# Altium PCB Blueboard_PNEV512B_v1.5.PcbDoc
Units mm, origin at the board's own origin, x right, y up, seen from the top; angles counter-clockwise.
Board outline 183.2 x 34.6 mm, 2 copper layers (Top Layer, Bottom Layer), stack 1.62 mm thick; 130 components, 72 nets, 392 pads, 149 vias.
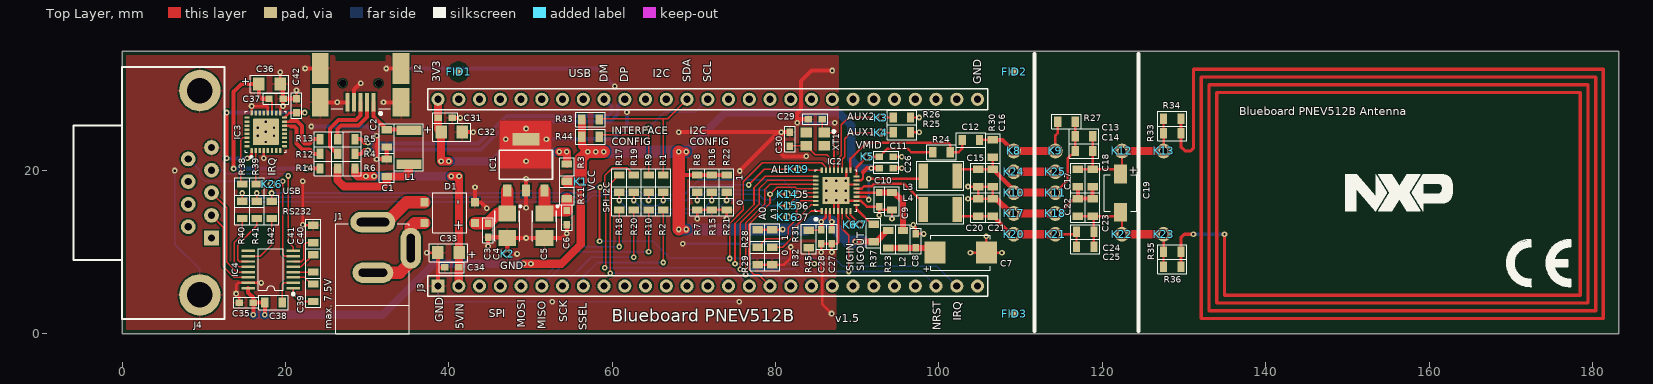
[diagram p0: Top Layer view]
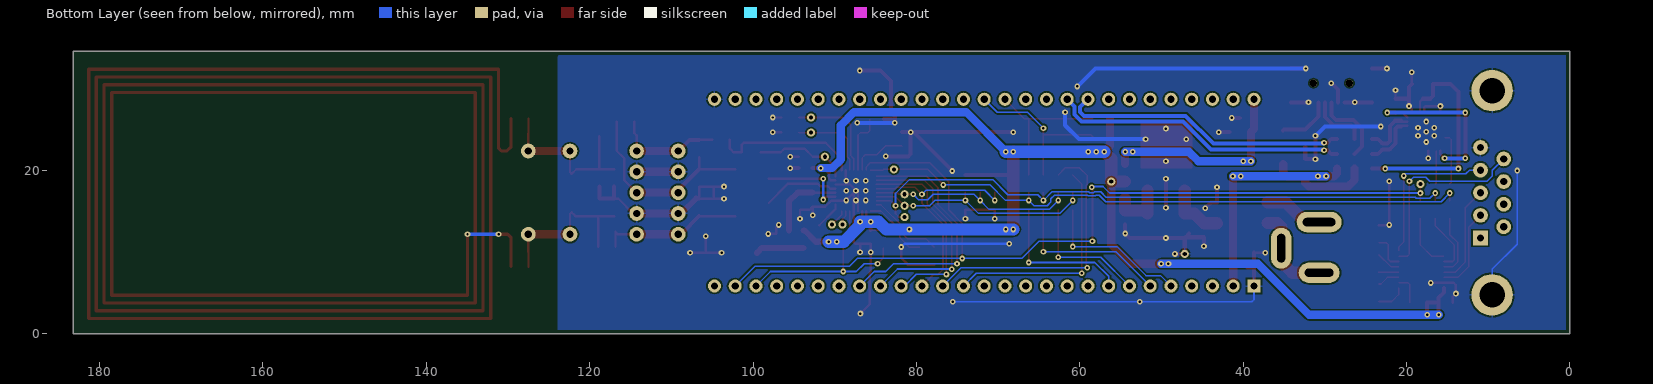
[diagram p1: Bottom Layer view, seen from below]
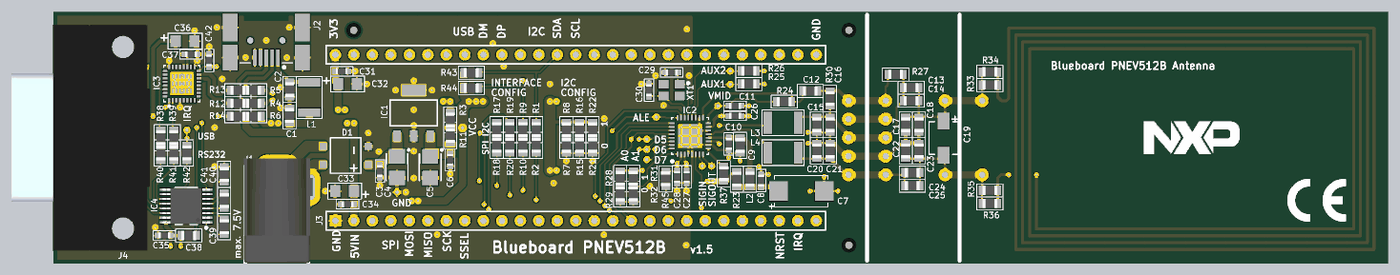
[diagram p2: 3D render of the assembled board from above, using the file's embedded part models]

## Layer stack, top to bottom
Top Layer: signal copper 0.035
Dielectric: core 1.55, FR-4, Dk 4.3
Bottom Layer: signal copper 0.035

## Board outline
0,0 183.2,0 183.2,34.6 0,34.6

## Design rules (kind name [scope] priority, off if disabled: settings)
Clearance [All] p1: gap=0.2
ComponentClearance [All] p1: gap=0 collisioncheckmode=3 verticalgap=0 showdistances=FALSE
DiffPairsRouting [(InDifferentialPairClass('All Differential Pairs'))] p1: maxlimit=0.2 minlimit=0.2 mostfreqgap=0.2 maxuncoupledlength=12.7
FabricationTestPointUsage TestPointUsage [All] p1: valid=0 allowmultiple=FALSE
FabricationTestpoint Testpoint [All] p1: side=3 testpointundercomponent=TRUE minsize=1.016 maxsize=2.54 preferedsize=1.524 minholesize=0 maxholesize=1.016 preferedholesize=0.813 testpointgrid=0.025 allowsidetop=TRUE allowsidebottom=TRUE usegrid=TRUE gridtolerance=0
HoleSize [All] p1: absolutevalues=TRUE maxlimit=6.3 minlimit=0.1 maxpercent=80.000 minpercent=20.000
PlaneClearance [All] p1: clearance=0.5
PlaneConnect [All] p1: planeconnectstyle=Relief reliefexpansion=0.2 reliefentries=4 reliefconductorwidth=0.2 reliefairgap=0.2
PolygonConnect PolygonConnect_Via [IsVia] p1: connectstyle=Direct reliefconductorwidth=0.254 reliefentries=4 polygonreliefangle="90 Angle"
PolygonConnect [All] p2: connectstyle=Relief reliefconductorwidth=0.25 reliefentries=4 polygonreliefangle="90 Angle"
RoutingVias [All] p1: holewidth=0.3 width=0.7 viastyle="Through Hole" minholewidth=0.3 minwidth=0.7 maxholewidth=0.6 maxwidth=1
SilkscreenOverComponentPads [All] p1: minsilkscreentomaskgap=0.254
SolderMaskExpansion SolderMaskExpansion_Via [IsVia] p1: expansion=-0.1
SolderMaskExpansion [All] p2: expansion=0.1
Width Width_DiffPair [(InDifferentialPairClass('All Differential Pairs'))] p1: maxlimit=0.5 minlimit=0.3 preferedwidth=0.5
Width [All] p2: maxlimit=3 minlimit=0.2 preferedwidth=0.2
20 further rules are at their usual default settings.

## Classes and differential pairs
differential pair USB: +USB_P -USB_N
differential pair LPC_USB: +LPC_USB_P -LPC_USB_N

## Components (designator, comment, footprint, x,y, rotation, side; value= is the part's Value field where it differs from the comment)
C1 "1uF" Y0805 32.4,20.35 r270 top
C2 "1uF" Y0805 32.4,23.95 r90 top
C3 "100nF" Y0603 44.8,12.7 r270 top
C4 "33uF/16V" C_TANTAL_B 47.15,13.25 r270 top
C5 "33uF/16V" C_TANTAL_B 51.7,13.25 r270 top
C6 "100nF" Y0603 54.45,14.25 r270 top
C7 "100uF" C_TANTAL_D 102.65,9.95 r0 top
C8 "100nF" Y0603 97.15,11.4 r270 top
C9 "1uF" Y0805 94.25,16.25 r90 top
C10 "100nF" Y0603 92.7,16.45 r90 top
C11 "100nF" Y0603 93.55,21.7 r0 top
C12 "1nF" Y0805 103.9,23.75 r0 top
C13 "12pF" Y0805 117.75,24.2 r0 top
C14 "33pF" Y0805 117.75,22.4 r0 top
C15 "100pF" Y0805 104.8,19.1 r90 top
C16 "56pF" Y0805 106.6,19.1 r90 top
C17 "100pF" Y0805 117,19.1 r90 top
C18 "39pF" Y0805 118.8,19.1 r90 top
C19 "TZB4A 25pF" C_TZB4_A 122.2,17.25 r270 top
C20 "100pF" Y0805 104.8,15.5 r90 top
C21 "56pF" Y0805 106.6,15.5 r90 top
C22 "100pF" Y0805 117,15.5 r90 top
C23 "39pF" Y0805 118.8,15.5 r90 top
C24 "33pF" Y0805 117.9,12.5 r0 top
C25 "12pF" Y0805 117.9,10.7 r0 top
C26 "100nF" Y0603 93.55,20.3 r180 top
C27 "100nF" Y0603 86.9,11.9 r90 top
C28 "100nF" Y0603 85.6,11.9 r90 top
C29 "15pF" Y0603 84.85,26.3 r0 top
C30 "15pF" Y0603 81.75,23.85 r270 top
C31 "100nF" Y0603 39.55,26.45 r180 top
C32 "10uF/10V" CAP_TANT_1206_CASE-A 40.35,24.7 r0 top
C33 "10uF/10V" CAP_TANT_1206_CASE-A 39.95,9.95 r180 top
C34 "100nF" Y0603 40.35,8.15 r0 top
C35 "100nF" Y0603 15.2,3.85 r180 top
C36 "10uF/10V" CAP_TANT_1206_CASE-A 18.05,30.6 r0 top
C37 "100nF" Y0603 18.85,28.8 r180 top
C38 "1uF" Y0805 18.55,3.85 r0 top
C39 "1uF" Y0805 23.4,5.05 r90 top
C40 "1uF" Y0805 23.4,12.25 r90 top
C41 "1uF" Y0805 23.4,8.65 r90 top
C42 "100nF" Y0603 21.35,27.95 r270 top
D1 "CDBHM240L" GRETZ_MBS2 40.1,14.85 r270 top
FID1 "{Value}" FIDUCIAL_40 41.2,32.1 r0 top
FID2 "{Value}" FIDUCIAL_40 109.2,32.1 r0 top
FID3 "{Value}" FIDUCIAL_40 109.2,2.5 r0 top
IC1 "LM3940IMP-3.3" SOT-223-3 47.15,17.55 r0 top
IC2 "PN512" QFN50P500X500X100-32N 87.4,17.55 r90 top
IC3 "FT232RQ" QFN-32_FTDI 17.6,24.75 r90 top
IC4 "SP3232" TSSOP-PW_16_065 18.2,7.9 r180 top
J1 "PWR_DC_PJ-202B" CON_JCK_2.5mm 30.7,7.5 r90 top locked
J2 "USB_Mini_B" CON_USB-B-MINI_SD-67503-010 29.2,28.35 r270 top locked
J3 "LPCXpresso" "CON_LPCXpresso 2X27" 71.7,17.3 r0 top locked
J4 "DSUB 9F" CON_DB9_F 10.95,11.75 r90 top locked
K1 "TP1" TESTP_ROUND_1.0mm#1 56.15,18.65 r90 top
K2 "TP1" TESTP_ROUND_1.0mm#1 47.15,9.8 r180 top
K3 "TP1" TESTP_ROUND_1.0mm#1 92.9,26.5 r270 top
K4 "TP1" TESTP_ROUND_1.0mm#2 92.95,26.65 r0 top
K5 "TP1" TESTP_ROUND_1.0mm#1 91.2,21.7 r90 top
K6 "TP1" TESTP_ROUND_1.0mm#1 89.05,13.4 r0 top
K7 "TP1" TESTP_ROUND_1.0mm#1 90.35,13.4 r0 top
K8 "TP_0.9mm" TP_0.9mm 109.15,22.4 r0 top
K9 "TP_0.9mm" TP_0.9mm 114.25,22.4 r0 top
K10 "TP_0.9mm" TP_0.9mm 109.149,17.302 r0 top
K11 "TP_0.9mm" TP_0.9mm 114.249,17.302 r0 top
K12 "TP_0.9mm" TP_0.9mm 122.4,22.4 r90 top
K13 "TP_0.9mm" TP_0.9mm 127.5,22.4 r0 top
K14 "TP1" TESTP_ROUND_1.0mm#1 81.45,17.1 r90 top
K15 "TP1" TESTP_ROUND_1.0mm#1 81.45,15.7 r90 top
K16 "TP1" TESTP_ROUND_1.0mm#1 81.45,14.3 r90 top
K17 "TP_0.9mm" TP_0.9mm 109.149,14.752 r0 top
K18 "TP_0.9mm" TP_0.9mm 114.249,14.752 r0 top
K19 "TP1" TESTP_ROUND_1.0mm#1 82.75,20.15 r90 top
K20 "TP_0.9mm" TP_0.9mm 109.149,12.202 r0 top
K21 "TP_0.9mm" TP_0.9mm 114.249,12.202 r0 top
K22 "TP_0.9mm" TP_0.9mm 122.4,12.2 r0 top
K23 "TP_0.9mm" TP_0.9mm 127.5,12.2 r0 top
K24 "TP_0.9mm" TP_0.9mm 109.149,19.863 r0 top
K25 "TP_0.9mm" TP_0.9mm 114.249,19.863 r0 top
K26 "TP1" TESTP_ROUND_1.0mm#1 18.3,18.35 r0 top
L1 "100nH" INDCC_1812 35.1,22.85 r270 top
L2 "22nH" Y0805 95.6,11.6 r270 top
L3 "470nH / shielded (1210)" INDCC_1812 100.15,19.35 r0 top
L4 "470nH / shielded (1210)" INDCC_1812 100.15,15.25 r0 top
R1 "0R DNP" Y0805 66.25,18.4 r270 top
R2 "0R" Y0805 66.25,16.25 r270 top
R3 "0R" Y0805 54.45,19.75 r90 top
R4 "0R" Y0805 27.45,22.05 r0 top
R5 "0R" Y0805 27.45,23.85 r0 top
R6 "0R" Y0805 27.45,20.25 r0 top
R7 "1k DNP" Y0805 70.4,16.25 r90 top
R8 "1k DNP" Y0805 70.4,18.4 r90 top
R9 "0R DNP" Y0805 64.45,18.4 r270 top
R10 "0R" Y0805 64.45,16.25 r270 top
R11 "0R DNP" Y0805 54.45,17.6 r90 top
R12 "0R DNP" Y0805 25.3,22.05 r0 top
R13 "0R DNP" Y0805 25.3,23.85 r0 top
R14 "0R DNP" Y0805 25.3,20.25 r0 top
R15 "1k DNP" Y0805 72.2,16.25 r90 top
R16 "1k DNP" Y0805 72.2,18.4 r90 top
R17 "0R DNP" Y0805 60.85,18.4 r270 top
R18 "0R" Y0805 60.85,16.25 r270 top
R19 "0R DNP" Y0805 62.65,18.4 r270 top
R20 "0R" Y0805 62.65,16.25 r270 top
R21 "1k DNP" Y0805 74,16.25 r90 top
R22 "1k DNP" Y0805 74,18.4 r90 top
R23 "0R" Y0805 93.8,11.6 r90 top
R24 "1k" Y0805 100.3,22.25 r180 top
R25 "DNP" Y0805 95.45,24.7 r180 top
R26 "DNP" Y0805 95.45,26.5 r180 top
R27 "2k7" Y0805 115.6,26 r180 top
R28 "0R" Y0805 77.8,11.7 r270 top
R29 "0R DNP" Y0805 77.8,9.55 r270 top
R30 "DNP" Y0805 106.6,22.7 r270 top
R31 "0R DNP" Y0805 79.6,11.7 r270 top
R32 "0R" Y0805 79.6,9.55 r270 top
R33 "4R42" Y0805 128.55,24.55 r180 top
R34 "4R42" Y0805 128.55,26.35 r180 top
R35 "4R42" Y0805 128.55,10.05 r180 top
R36 "4R42" Y0805 128.55,8.25 r180 top
R37 "0R DNP" Y0805 92,12.35 r90 top
R38 "0R DNP" Y0805 14.7,17.3 r90 top
R39 "0R DNP" Y0805 16.5,17.3 r90 top
R40 "0R DNP" Y0805 14.7,15.2 r90 top
R41 "0R DNP" Y0805 16.5,15.2 r90 top
R42 "0R DNP" Y0805 18.3,15.2 r270 top
R43 "10k" Y0805 57.35,26.25 r0 top
R44 "10k" Y0805 57.35,24.15 r0 top
R45 "10k" Y0805 84.049,11.633 r270 top
XT1 "27.12MHz" QUARTZ_32SMX 84.85,23.85 r180 top

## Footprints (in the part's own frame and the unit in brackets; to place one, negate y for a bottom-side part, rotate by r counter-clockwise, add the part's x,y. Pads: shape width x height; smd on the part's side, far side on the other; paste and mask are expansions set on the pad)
C_TANTAL_B [mm] "Capacitor, SM Tantalum; Body 3.5 x 2.8 mm, Size B"
  rect 2x2.2 smd: 1(-1.5,0) 2(1.5,0)
  silkscreen extent -2.5,-1.5 1.85,1.73, body extent -1.85,-1.5 1.85,1.5, height 2.11
C_TANTAL_D [mm]
  rect 2.55x2.7 smd: 1(-3.15,0) 2(3.15,0)
  silkscreen extent -3.65,-2.15 3.65,2.15, body extent -3.8,-2.25 3.8,2.25, height 3.11
C_TZB4_A [mm] "Murata Ceramic Trimmer Capacitors TZB4 Series, Type A"
  rect 2.3x1.6 smd: 1(-2.35,0) 2(2.35,0)
  silkscreen extent -2.25,-2 2.25,2, body extent -2.25,-2 2.25,2, height 3
CAP_TANT_1206_CASE-A [mm] "AVX"
  rect 1.4x1.6 smd: 1(-1.3,0) 2(1.3,0)
  silkscreen extent -2.34,-1.1 2.34,1.1
CON_DB9_F [mm]
  rect 1.8x1.8 hole 0.9: 1(0,0)
  round 1.8 hole 0.9: 2(2.769,0) 3(5.537,0) 4(8.306,0) 5(11.074,0) 6(1.372,2.845) 7(4.14,2.845) 8(6.909,2.845) 9(9.677,2.845)
  round 5.08 hole 3.1: 10(-6.96,1.422) 11(18.034,1.422)
  silkscreen extent -9.9,-1.59 20.95,16.92, body extent -10,-2.25 21.1,16.74, height 12.42
CON_JCK_2.5mm [mm]
  oval 2.5x5.5 hole 1 slot 4 at 90 deg: 1(6.2,0)
  oval 2.5x5 hole 1 slot 3.5 at 90 deg: 2(0,0)
  oval 5x2.5 hole 1 slot 3.5 at 0 deg: 3(3,-4.65)
  silkscreen extent -7.5,-4.45 6,4.55, body extent -7.5,-4.86 6.98,4.61, height 11.18
"CON_LPCXpresso 2X27" [mm]
  rect 1.6x1.6 hole 0.9: 1(-33.02,-11.43)
  round 1.6 hole 0.9: 2(-30.48,-11.43) 3(-27.94,-11.43) 4(-25.4,-11.43) 5(-22.86,-11.43) 6(-20.32,-11.43) 7(-17.78,-11.43) 8(-15.24,-11.43) 9(-12.7,-11.43) 10(-10.16,-11.43) 11(-7.62,-11.43) 12(-5.08,-11.43) 13(-2.54,-11.43) 14(0,-11.43) 15(2.54,-11.43) 16(5.08,-11.43) 17(7.62,-11.43) 18(10.16,-11.43) 19(12.7,-11.43) 20(15.24,-11.43) 21(17.78,-11.43) 22(20.32,-11.43) 23(22.86,-11.43) 24(25.4,-11.43) 25(27.94,-11.43) 26(30.48,-11.43) 27(33.02,-11.43) 28(-33.02,11.43) 29(-30.48,11.43) 30(-27.94,11.43) 31(-25.4,11.43) 32(-22.86,11.43) 33(-20.32,11.43) 34(-17.78,11.43) 35(-15.24,11.43) 36(-12.7,11.43) 37(-10.16,11.43) 38(-7.62,11.43) 39(-5.08,11.43) 40(-2.54,11.43) 41(0,11.43) 42(2.54,11.43) 43(5.08,11.43) 44(7.62,11.43) 45(10.16,11.43) 46(12.7,11.43) 47(15.24,11.43) 48(17.78,11.43) 49(20.32,11.43) 50(22.86,11.43) 51(25.4,11.43) 52(27.94,11.43) 53(30.48,11.43) 54(33.02,11.43)
  silkscreen extent -34.29,-12.7 34.29,12.7
CON_USB-B-MINI_SD-67503-010 [mm] "Molex"
  rect 2.25x0.5 smd: 1(0,1.6) 2(0,0.8) 3(0,0) 4(0,-0.8) 5(0,-1.6)
  rect 3.8x2.05 smd: 6(-4.15,4.95) 9(-4.15,-4.95)
  rect 3.5x2.05 smd: 7(0,4.95) 8(0,-4.95)
  round 0.9 hole 0.9 unplated: 10(-2.35,2.2) 11(-2.35,-2.2)
  Top Layer pour cut-out: -6.25,3.1 -5.05,3.1 -5.05,-3.1 -6.25,-3.1
  silkscreen extent 0.75,-3.6 1.5,3.6
FIDUCIAL_40 [mm]
  round 1 smd: 1(0,0)
  Top Layer pour cut-out: 0,1.27 -0.153,1.261 -0.304,1.233 -0.45,1.187 -0.59,1.125 -0.721,1.045 -0.842,0.951 -0.951,0.842 -1.045,0.721 -1.125,0.59 -1.187,0.45 -1.233,0.304 -1.261,0.153 -1.27,0 -1.261,-0.153 -1.233,-0.304 -1.187,-0.45 -1.125,-0.59 -1.045,-0.721 -0.951,-0.842 -0.842,-0.951 -0.721,-1.045 -0.59,-1.125 -0.45,-1.187 -0.304,-1.233 -0.153,-1.261 0,-1.27 0.153,-1.261 0.304,-1.233 0.45,-1.187 0.59,-1.125 0.721,-1.045 0.842,-0.951 0.951,-0.842 1.045,-0.721 1.125,-0.59 1.187,-0.45 1.233,-0.304 1.261,-0.153 1.27,0 1.261,0.153 1.233,0.304 1.187,0.45 1.125,0.59 1.045,0.721 0.951,0.842 0.842,0.951 0.721,1.045 0.59,1.125 0.45,1.187 0.304,1.233 0.153,1.261
GRETZ_MBS2 [mm]
  rect 1x1 smd: 1(-1.27,-3.099) 2(1.27,-3.099) 3(1.27,3.099) 4(-1.27,3.099)
  silkscreen extent -2.45,-2.1 2.45,2.1
INDCC_1812 [mil]
  rect 45x120 smd: 1(-82,0) 2(82,0)
  silkscreen extent -114,-70 114,70
QFN50P500X500X100-32N [mm] "QFN, 32-Leads, Body 5.1x5.1mm (max), Pitch 0.50mm, IPC Medium Density"
  rect 0.7x0.25 smd: 1(-2.5,1.75) 2(-2.5,1.25) 3(-2.5,0.75) 4(-2.5,0.25) 5(-2.5,-0.25) 6(-2.5,-0.75) 7(-2.5,-1.25) 8(-2.5,-1.75) 17(2.5,-1.75) 18(2.5,-1.25) 19(2.5,-0.75) 20(2.5,-0.25) 21(2.5,0.25) 22(2.5,0.75) 23(2.5,1.25) 24(2.5,1.75)
  rect 0.25x0.7 smd: 9(-1.75,-2.5) 10(-1.25,-2.5) 11(-0.75,-2.5) 12(-0.25,-2.5) 13(0.25,-2.5) 14(0.75,-2.5) 15(1.25,-2.5) 16(1.75,-2.5) 25(1.75,2.5) 26(1.25,2.5) 27(0.75,2.5) 28(0.25,2.5) 29(-0.25,2.5) 30(-0.75,2.5) 31(-1.25,2.5) 32(-1.75,2.5)
  rect 3.3x3.3 smd paste-5 mask+0.102: 33(0,0)
  silkscreen extent -3.65,-2.55 2.55,2.6, body extent -2.55,-2.55 2.55,2.55, height 1
QFN-32_FTDI [mm]
  rect 0.3x0.3 smd: 1(-2.45,1.75) 8(-2.45,-1.75) 9(-1.75,-2.45) 16(1.75,-2.45) 17(2.45,-1.75) 24(2.45,1.75) 25(1.75,2.45) 32(-1.75,2.45)
  rrect50% 0.6x0.3 smd: 1(-2.3,1.75) 8(-2.3,-1.75) 17(2.3,-1.75) 24(2.3,1.75)
  rect 0.6x0.3 smd: 2(-2.3,1.25) 3(-2.3,0.75) 4(-2.3,0.25) 5(-2.3,-0.25) 6(-2.3,-0.75) 7(-2.3,-1.25) 18(2.3,-1.25) 19(2.3,-0.75) 20(2.3,-0.25) 21(2.3,0.25) 22(2.3,0.75) 23(2.3,1.25)
  rrect50% 0.3x0.6 smd: 9(-1.75,-2.3) 16(1.75,-2.3) 25(1.75,2.3) 32(-1.75,2.3)
  rect 0.3x0.6 smd: 10(-1.25,-2.3) 11(-0.75,-2.3) 12(-0.25,-2.3) 13(0.25,-2.3) 14(0.75,-2.3) 15(1.25,-2.3) 26(1.25,2.3) 27(0.75,2.3) 28(0.25,2.3) 29(-0.25,2.3) 30(-0.75,2.3) 31(-1.25,2.3)
  rrect6% 3.2x3.2 smd paste-5: 33(0,0)
  silkscreen extent -3.2,-2.5 2.5,2.5, body extent -2.5,-2.5 2.5,2.5, height 0.9
QUARTZ_32SMX [mm]
  rect 1.4x1.2 smd: 1(-1.1,-0.8) 2(1.1,-0.8) 3(1.1,0.8) 4(-1.1,0.8)
  silkscreen extent -2.42,-1.1 -2.13,-0.8, body extent -1.6,-1.2 1.6,1.2, height 0.6
SOT-223-3 [mm]
  rect 1x1.5 smd: 1(0,0) 2(2.286,0) 3(4.572,0)
  rect 3.3x1.5 smd: 4(2.286,6.299)
  silkscreen extent -0.97,1.37 5.54,4.93
TESTP_ROUND_1.0mm#1 [mm]
  round 1 hole 0.5 paste-2: 1(0,0)
TESTP_ROUND_1.0mm#2 [mm]
  round 1 hole 0.5 paste-2: 1(-0.05,-2)
TP_0.9mm [mm]
  round 1.8 hole 0.9: 1(0,0)
TSSOP-PW_16_065 [mm]
  rect 1.65x0.3 smd: 1(-2.775,2.275) 2(-2.775,1.625) 3(-2.775,0.975) 4(-2.775,0.325) 5(-2.775,-0.325) 6(-2.775,-0.975) 7(-2.775,-1.625) 8(-2.775,-2.275) 9(2.775,-2.275) 10(2.775,-1.625) 11(2.775,-0.975) 12(2.775,-0.325) 13(2.775,0.325) 14(2.775,0.975) 15(2.775,1.625) 16(2.775,2.275)
  silkscreen extent -2.9,-2.55 1.55,3.15, body extent -3.23,-2.5 3.23,2.5, height 1.2
Y0603 [mm]
  rect 0.9x0.8 smd: 1(-0.864,0) 2(0.864,0)
  silkscreen extent -1.55,-0.65 1.55,0.65, body extent -0.81,-0.42 0.81,0.4, height 0.46
Y0805 [mm]
  rect 0.9x1.27 smd: 1(-1.067,0) 2(1.067,0)
  silkscreen extent -1.8,-0.9 1.8,0.9, body extent -1.02,-0.65 1,0.62, height 0.61

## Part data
C1 C2 C9 C12 C13 C14 C15 C16 C17 C18 C20 C21 C22 C23 C24 C25 C38 C39 C40 C41: library part CAPC0805, "CAPC0805"
C3 C6 C8 C10 C11 C26 C27 C28 C29 C30 C31 C34 C35 C37 C42: library part CAPC0603, "CAPC0603"
C4 C5: library part C_TANTAL_B, "C_TANTAL_B"
C7: library part C_TANTAL_D, "C_TANTAL_D"
C19: library part C_TRIMM, "C_TRIMM"
C32 C33 C36: library part C_TANTAL_1206, "C_TANTAL_1206"
D1: library part GRETZ_MBS2, "GRETZ_MBS2_Schottky"
FID1 FID2 FID3: library part FIDUCIAL, "FIDUCAL"
IC1: library part LM3940-3.3, "LM3940-3.3"
IC3: library part FT232R, "FT232R"
J1: library part CON_JCK_2.5mm, "PWR_JACK_2.5mm x 5.5mm"
J2: library part CON_USB_B_RA, "CON_USB_B_RA"
J3: library part CON_LPCXpresso, "CON_LPCXpresso 2X27"
J4: library part CON_DB9_F, "DB9_FEMALE"
L1 L3 L4: library part INDC1812, "INDC1812"
L2: library part INDC0805, "INDC0805"
R1 R2 R3 R4 R5 R6 R7 R8 R9 R10 R11 R12 R13 R14 R15 R16 R17 R18 R19 R20 R21 R22 R23 R24 R25 R26 R27 R28 R29 R30 R31 R32 R33 R34 R35 R36 R37 R38 R39 R40 R41 R42 R43 R44 R45: library part RESC0805, "RESC0805"
XT1: library part QUARTZ_32SMX, "QUARTZ_32SMX"

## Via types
v1: diameter 0.7, hole 0.3, Top Layer to Bottom Layer, 140 vias
v2: diameter 0.7, hole 0.3, Top Layer to Bottom Layer, tented top, 9 vias

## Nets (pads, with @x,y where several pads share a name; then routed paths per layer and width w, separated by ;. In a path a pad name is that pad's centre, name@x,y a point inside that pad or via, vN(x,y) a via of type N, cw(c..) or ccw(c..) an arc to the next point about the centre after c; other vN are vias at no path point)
+3.3VLPC: C31.2 C32.1 J3.28 R3.2 | length 27
  Top Layer w1: J3.28 38.68,26.456 C31.2 38.686,25.064 C32.1 v1(39.05,21.15) v1(40,21.15) ; v1(53.5,22.3) v1(54.45,22.3) R3.2
  Bottom Layer w1: v1(39.05,21.15) v1(40,21.15) 45.5,21.15 46.65,22.3 v1(53.5,22.3) v1(54.45,22.3)
+5VLPC: C33.1 C34.2 J3.2 R6.2 | length 28.9
  Top Layer w1: R6.2 28.517,19.633 28.85,19.3 v1(29.85,19.3) v1(30.85,19.3) ; v1(40.3,19.3) v1(41.25,19.3) C33.1 41.25,8.186 C34.2 41.214,5.876 J3.2
  Bottom Layer w1: v1(29.85,19.3) v1(30.85,19.3) v1(40.3,19.3) v1(41.25,19.3)
ALE: IC2.24 K19.1 R1.2 R2.1 R38.1 R40.2 | length 76.4
  Top Layer w0.2: R40.2 v1(14.7,17.25) ; v1(66.25,16.35) R2.1 R1.2 ; v1(76.7,18.25) 78.6,20.15 K19.1 84,20.15 84.1,20.05 IC2.24
  Bottom Layer w0.2: v1(14.7,17.25) 15.75,16.2 56.816,16.2 57.616,17 58.02,17 58.112,16.908 58.982,16.908 59.074,17 63.1,17 63.55,16.55 63.55,16.15 64,15.7 65.6,15.7 v1(66.25,16.35) 69.1,16.35 71,18.25 v1(76.7,18.25)
D5: IC2.29 K14.1 R15.2 R16.1 R19.2 R20.1 | length 26
  Top Layer w0.2: v1(62.65,16.35) R20.1 R19.2 ; v1(72.2,16.35) R15.2 ; v1(80.4,17.1) K14.1 82.15,17.1 82.35,17.3 IC2.29
  Bottom Layer w0.2: v1(62.65,16.35) 63.75,15.25 71.1,15.25 v1(72.2,16.35) 72.95,17.1 77.95,17.1 78.6,16.45 79.75,16.45 v1(80.4,17.1)
D6: IC2.30 K15.1 R17.2 R18.1 R21.2 R22.1 | length 28
  Top Layer w0.2: v1(60.85,16.35) R18.1 R17.2 ; v1(74,16.35) R21.2 ; v1(80.4,15.7) K15.1 82.55,16.8 IC2.30
  Bottom Layer w0.2: v1(60.85,16.35) 62.4,14.8 72.45,14.8 v1(74,16.35) 77.75,16.35 78.4,15.7 v1(80.4,15.7)
D7: IC2.31 K16.1 R9.2 R10.1 R39.1 R41.2 | length 77.3
  Top Layer w0.2: R39.1 R41.2 v1(16.5,17.25) ; v1(64.45,16.35) R10.1 R9.2 ; K16.1 82.1,14.3 82.55,14.75 v1(82.55,15.7) 83.15,16.3 IC2.31
  Bottom Layer w0.2: v1(16.5,17.25) 17.15,16.6 18.8,16.6 18.95,16.75 56.8,16.75 57.45,17.4 58.186,17.4 58.278,17.308 58.816,17.308 58.908,17.4 63.4,17.4 v1(64.45,16.35) 65.15,17.05 68.8,17.05 70.65,18.9 80.85,18.9 82.55,17.2 v1(82.55,15.7)
GND: C1.1 C2.1 C3.2 C4.2 C5.2 C6.2 C7.2 C8.1 C9.1 C10.1 C11.2 C15.1 C16.1 C17.1 C18.1 C20.2 C21.2 C22.2 C23.2 C26.1 C27.1 C28.1 C29.1 C30.1 C31.1 C32.2 C33.2 C34.1 C35.2 C36.2 C37.1 C40.2 C42.1 D1.4 IC1.2 IC1.4 IC2.4 IC2.5 IC2.10 IC2.14 IC2.18 IC2.33 IC3.4 IC3.17 IC3.20 IC3.24 IC3.33 IC4.15 J2.4 J2.5 J2.6 J2.7 J2.8 J2.9 J3.1 J3.54 J4.5 J4.10 J4.11 K2.1 K17.1 K18.1 K24.1 K25.1 R7.1 R15.1 R21.1 R25.1 R26.1 R29.2 R32.2 | length 332.9
  Top Layer w0.3: C35.2 14.336,4.564 v1(13.95,4.95) 13.95,6 14.225,6.275 IC4.15 17.025,6.275 v1(17.05,6.25) ; IC3.24@15.85,27.05 15.85,27.2 v1(15.85,27.9) 17.7,27.9 17.85,27.75 IC3.20 ; v1(17.35,21.5) IC3.4 ; IC3.17@19.35,27.05 19.35,27.2 19.35,27.55 v1(19.7,27.9) v1@19.714,27.914 ; C36.2 v1(19.35,32.05) ; C42.1 v1(21.35,29.85) ; v1(22.1,18.7) v1(22.1,13.35) 22.133,13.317 C40.2 ; v1(37.3,9.95) C33.2 ; v1(70.4,14.1) R7.1 R15.1 R21.1 v1(74,14.1) ; R29.2 R32.2 81.033,8.483 81.85,9.3 v1(81.85,10.65) ; v1(86.85,2.5) 85.7,3.65 85.7,7.55 85.6,7.65 v1(85.6,10) C28.1 C27.1 ; v1(86.9,10) C27.1 ; IC2.4 87.15,17.3 v2(87.4,17.55) ; IC2.18 88.65,18.8 v2(88.6,18.75) IC2.33@88.15,18.3 ; IC2.14 IC2.33@88.15,18.3 ; v1(92.7,14.55) C10.1 ; v1(94.25,14.1) C9.1 93.103,15.183 C10.1 ; C11.2 v1(95.45,21.7) ; R25.1 v1(97.6,24.7) ; R26.1 v1(97.6,26.5) ; v1(96.85,13.35) 97.15,13.05 C8.1 98.136,12.264 v1(98.15,12.25) ; v1(103.55,16.55) 103.567,16.567 C20.2 ; v1(103.55,18.05) 103.567,18.033 C15.1 ; v1(103.85,9.95) C7.2 ; v1(105.8,11.95) C7.2 ; v1(107.7,9.95) C7.2 ; K18.1 114.676,14.752 116.49,16.567 C22.2 ; C27.1 87.486,11.036 87.65,11.2 IC2.5 IC2.33@87.65,17.3 ; v2(87.4,17.55) IC2.33@88.15,18.3 ; v2(87.4,17.55) IC2.33@87.65,17.3 ; IC2.33@87.65,17.3 v2(88.6,16.35) 88.65,16.3 IC2.10 90.45,16.3 91.164,15.586 C10.1 ; C20.2 C15.1 ; C20.2 C21.2 C16.1 C15.1
  Top Layer w0.5: C36.2 19.714,30.236 C37.1 ; v1@19.714,27.914 C37.1 ; C42.1 21.336,28.8 C37.1 ; v1(22.4,32.5) J2.9 ; J2.8 v1(26.35,28.35) J2.5 ; J2.4 28.4,29.9 v1(29.2,30.7) ; v1(31.15,24.25) v1(31.15,21.4) 31.167,21.417 C1.1 C2.1 ; v1(32,28.35) J2.7 ; v1(32.35,32.5) J2.6 ; C33.2 38.65,8.35 38.85,8.15 ; J3.1 38.68,7.98 38.85,8.15 ; C34.1 38.85,8.15 ; C31.1 v1(41.4,26.45) ; C32.2 v1(43,24.7) ; v1(43.2,17.95) 43.199,17.949 D1.4 43.93,16.12 v1(44.65,15.4) ; v1(44.8,10.75) C3.2 C4.2@47.064,11.836 ; C4.2@46.614,12.286 C4.2@47.064,11.836 ; v1(46.95,23.85) IC1.4 ; v1(48.35,9.8) K2.1 C4.2 ; v1(49.45,15.45) 49.436,15.464 IC1.2 49.436,18.986 v1(49.45,19) ; v1(49.45,21.15) 49.436,21.164 IC1.4 ; v1(49.45,25.15) 49.436,25.136 IC1.4 ; v1(51.95,23.85) IC1.4 ; C6.2 v1(54.45,12.3) 53.9,11.75 C5.2 v1(49.45,11.75) C4.2 ; v1(68.15,24.7) 80.35,24.7 ; v1(75.6,19.95) 80.35,24.7 ; C30.1 80.714,24.714 v1(80.7,24.7) ; v1(83.75,21.75) 81,21.75 80.7,22.05 v1(80.7,24.7) ; C29.1 83.1,26.3 v1(82.65,25.85) 82.65,27 83.11,27.46 83.11,30.96 84.4,32.25 v1(86.95,32.25) ; C26.1 v1(95.45,20.3) ; C21.2 C21.2@106.979,16.567 ; K17.1@108.794,14.752 K17.1 ; C17.1 C22.2 C23.2 C18.1 ; C4.2@47.064,11.836 C4.2 ; 80.35,24.7 v1(80.7,24.7)
  Top Layer w0.75: C21.2@106.979,16.567 K17.1@108.794,14.752
  Top Layer w1: K17.1 K18.1 ; K24.1 K25.1
  Bottom Layer w0.2: v1(6.45,20) 6.45,11 9.528,7.922 J4.10 ; J3.1 38.68,4.22 38.95,3.95 v1(52.65,3.95) v1(75.55,3.95)
  Bottom Layer w0.3: v1(68.65,11.05) 81.45,11.05 v1(81.85,10.65)
  Bottom Layer w0.5: v1(23.15,25.4) 30,25.4 v1(31.15,24.25) ; v1(32.35,32.5) 58.1,32.5 v1(60.3,30.3) ; v1(51.95,23.85) 60.1,23.85 61.8,25.55 v1(61.8,27.15) ; v1(82.65,25.85) v1(87.25,25.85)
  other v1: 17.6,23.5 16.6,24.25 18.6,24.25 17.6,24.75 16.6,25.25 18.6,25.25 17.6,26
  other v2: 86.2,16.35 87.4,16.35 86.2,17.55 88.6,17.55 86.2,18.75 87.4,18.75
IRQ: IC2.23 J3.26 K26.1 R42.1 | length 117.3
  Top Layer w0.2: R42.1 v1(18.3,17.25) K26.1 ; v1(58.45,11.35) 58.45,18.05 58.542,17.958 v1(58.547,17.958) ; v1(74.377,9.24) 74.377,13.527 76.05,15.2 76.05,18.65 78.35,20.95 85.649,20.95 86.15,20.449 IC2.23
  Bottom Layer w0.2: v1(18.3,17.25) 56.35,17.25 57.15,18.05 58.455,18.05 v1(58.547,17.958) ; v1(58.45,11.35) 65,11.35 67.1,9.25 87.25,9.25 88.2,8.3 99.75,8.3 J3.26
LPC_5: J3.5 R18.2 | length 18.5
  Top Layer w0.2: v1(60.85,10.7) R18.2
  Bottom Layer w0.2: J3.5 50.12,7.15 51.9,7.15 55.45,10.7 v1(60.85,10.7)
LPC_6: J3.6 R10.2 | length 19.9
  Top Layer w0.2: v1(64.45,10.05) R10.2
  Bottom Layer w0.2: J3.6 55.56,10.05 v1(64.45,10.05)
LPC_7: J3.7 R20.2 | length 16
  Top Layer w0.2: v1(62.65,9.4) R20.2
  Bottom Layer w0.2: J3.7 57.45,9.4 v1(62.65,9.4)
LPC_8: J3.8 R2.2 | length 18.1
  Top Layer w0.2: v1(66.25,8.75) R2.2
  Bottom Layer w0.2: J3.8 56.46,7.06 58.15,8.75 v1(66.25,8.75)
LPC_15: J3.15 R17.1 | length 27.6
  Top Layer w0.2: v1(59.75,7.45) 59.75,18.367 R17.1
  Bottom Layer w0.2: v1(59.75,7.45) 72.66,7.45 J3.15
LPC_16: J3.16 R19.1 | length 34.3
  Top Layer w0.2: v1(59.1,8.1) 59.197,8.197 59.197,18.227 59.1,18.324 59.1,19.4 60.05,20.35 61.767,20.35 R19.1
  Bottom Layer w0.2: v1(59.1,8.1) 74.55,8.1 J3.16
LPC_17: IC2.28 J3.17 R7.2 R8.1 | length 30.3
  Top Layer w0.2: v1(70.4,16.35) R7.2 ; J3.17 77.94,7.25 77.4,7.25 76.75,7.9 76.75,13.45 79.32,16.02 v1(79.32,17.1) 80.17,17.95 82.4,17.95 82.55,17.8 IC2.28
  Bottom Layer w0.2: v1(70.4,16.35) 71.65,17.6 78.82,17.6 v1(79.32,17.1)
LPC_18: IC2.27 J3.18 | length 24
  Top Layer w0.2: v1(76.327,7.29) 76.327,13.593 78.65,15.916 78.65,17.666 79.334,18.35 84.85,18.35 IC2.27
  Bottom Layer w0.2: v1@76.327,7.3 80,7.3 81.43,5.87 J3.18
LPC_19: IC2.26 J3.19 | length 27.7
  Top Layer w0.2: v1(75.677,7.94) 75.677,13.577 78,15.9 78,17.8 79,18.8 IC2.26
  Bottom Layer w0.2: v1@75.677,7.95 82.32,7.95 J3.19
LPC_20: IC2.25 J3.20 | length 31.4
  Top Layer w0.2: v1(75.027,8.59) 75.027,13.527 77.35,15.85 77.35,17.9 78.75,19.3 IC2.25
  Bottom Layer w0.2: v1@75.027,8.6 82.8,8.6 83.75,7.65 85.16,7.65 J3.20
LPC_40: J3.40 R1.1 R43.2 | length 18.6
  Top Layer w0.2: R43.2@58.417,26.35 66.25,26.35 ; R1.1 66.25,26.35 ; J3.40 66.78,26.35 66.25,26.35
LPC_41: J3.41 R9.1 R44.2 | length 20.6
  Top Layer w0.2: R44.2 58.667,24.4 64.45,24.4 ; R9.1 64.45,24.4 ; v1(64.45,25.2) 64.45,24.4
  Bottom Layer w0.2: v1(64.45,25.2) 66.4,27.15 70.12,27.15 J3.41
LPC_USB_N: J3.36 R5.2 | length 35.2
  Top Layer w0.5: R5.2 29.22,23.85 29.67,23.4 v1(30.1,23.4)
  Bottom Layer w0.5: v1(30.1,23.4) 30.2,23.3 43.65,23.3 47.05,26.7 59.5,26.7 59.95,27.15 59.95,27.78 J3.36
LPC_USB_P: J3.37 R4.2 | length 36.4
  Top Layer w0.5: R4.2 29.22,22.05 29.67,22.5 v1(30.1,22.5)
  Bottom Layer w0.5: v1(30.1,22.5) 30.2,22.6 43.94,22.6 47.34,26 59.79,26 60.65,26.86 60.65,27.84 J3.37
NetC1_2: C1.2 L1.2 R6.1 R14.2 | length 12.6
  Top Layer w1: R6.1 26.383,18.817 27.15,18.05 31.95,18.05 32.4,18.5 C1.2 34.583,19.283 35.1,19.8 L1.2
NetC2_2: C2.2 J2.1 L1.1 | length 6.7
  Top Layer w0.5: J2.1 30.8,26.617 C2.2 35.016,25.017 L1.1
NetC3_1: C3.1 C4.1 D1.3 IC1.1 | length 7.2
  Top Layer w1.5: D1.3@43.215,13.564 C3.1 45.986,14.75 C4.1 IC1.1
NetC5_1: C5.1 C6.1 IC1.3 R11.1 | length 7.1
  Top Layer w1.5: IC1.3 51.7,17.528 C5.1 52.064,15.114 C6.1 R11.1
NetC7_1: C7.1 C8.2 L2.2 R23.1 | length 5.9
  Top Layer w0.75: R23.1 L2.2 97.147,10.533 C8.2 98.914,10.536 C7.1
NetC9_2: C9.2 C10.2 IC2.12 L2.1 | length 9.7
  Top Layer w0.3: IC2.12 92.686,17.3 C10.2
  Top Layer w0.5: C9.2@94.247,17.314 C9.2
  Top Layer w0.75: C10.2 C9.2@94.247,17.314 ; C9.2 94.533,17.317 95.6,16.25 L2.1
NetC12_1: C12.1 IC2.17 R24.1 | length 18.2
  Top Layer w0.3: IC2.17 89.15,21.45 91.1,23.4 97.2,23.4 101.15,23.4 101.367,23.183 R24.1 102.4,22.25 102.833,22.683 C12.1
NetC12_2: C12.2 K8.1 K9.1 R27.2 R30.1 | length 13.6
  Top Layer w0.3: C12.2 106.583,23.75 R30.1 ; K9.1 114.25,24.3 114.533,24.583 R27.2
  Top Layer w0.5: R30.1 107.783,23.767 K8.1
  Top Layer w1: K8.1 K9.1
NetC13_1: C13.1 C14.1 C15.2 C16.2 K10.1 K11.1 L3.2 R27.1 R30.2 | length 24.6
  Top Layer w0.3: L3.2@102.183,20.167 C15.2 C16.2 R30.2 ; K10.1 K10.1@109.149,17.618 ; K11.1 115.748,18.801 115.748,21.465 C14.1 C13.1 116.683,25.984 R27.1
  Top Layer w0.5: C16.2 K10.1@109.149,17.618
  Top Layer w1: K10.1 K11.1
NetC13_2: C13.2 C14.2 C17.2 C18.2 C19.1 K12.1 K13.1 R33.2 R34.2 | length 21.4
  Top Layer w0.3: C17.2 C18.2 ; C13.2 C14.2 118.8,22.383 C18.2 ; K12.1 122.4,19.8 C19.1 121.633,20.167 C18.2 ; R34.2 R33.2 127.5,24.533 K13.1
  Top Layer w1: K12.1 K13.1
NetC19_2: C19.2 C22.1 C23.1 C24.2 C25.2 K22.1 K23.1 R35.2 R36.2 | length 21
  Top Layer w0.3: C22.1 C23.1 ; C25.2 C24.2 118.967,14.266 C23.1 ; K22.1 122.4,14.7 C19.2 121.733,14.433 C23.1 ; R36.2 R35.2 127.5,10.067 K23.1
  Top Layer w1: K22.1 K23.1
NetC20_1: C20.1 C21.1 C24.1 C25.1 K20.1 K21.1 L4.2 | length 17.5
  Top Layer w0.3: L4.2@102.183,14.433 C20.1 C21.1 ; K20.1@108.831,12.202 K20.1 ; K21.1 116.535,12.202 C24.1 C25.1
  Top Layer w0.5: C21.1 K20.1@108.831,12.202
  Top Layer w1: K20.1 K21.1
NetC29_2: C29.2 IC2.21 XT1.1 | length 7.4
  Top Layer w0.2: C29.2 85.714,24.886 XT1.1 86.85,24.65 87.15,24.35 IC2.21
NetC30_2: C30.2 IC2.22 XT1.3 | length 7
  Top Layer w0.2: C30.2 81.814,23.05 XT1.3 84.85,21.95 86.25,21.95 86.65,21.55 IC2.22
NetC38_2: C38.2 IC4.2 | length 3.7
  Top Layer w0.2: C38.2 19.617,6.067 19.825,6.275 IC4.2
NetC39_1: C39.1 IC4.1 | length 3.6
  Top Layer w0.2: IC4.1 20.975,4.825 21.817,3.983 C39.1
NetC39_2: C39.2 IC4.3 | length 2.8
  Top Layer w0.2: IC4.3 22.325,6.925 23.133,6.117 C39.2
NetC40_1: C40.1 IC4.6 | length 4.4
  Top Layer w0.2: IC4.6 21.975,8.875 22.25,9.15 22.25,10.95 22.483,11.183 C40.1
NetC41_1: C41.1 IC4.4 | length 2.4
  Top Layer w0.2: IC4.4 23.392,7.575 C41.1
NetC41_2: C41.2 IC4.5 | length 3
  Top Layer w0.2: IC4.5 21.908,8.225 C41.2
NetC42_2: C42.2 IC3.1 IC3.16 | length 21.6
  Top Layer w0.3: v1(15.35,21.5) 15.85,22 15.85,22.3 IC3.1@15.85,22.45 ; IC3.16@19.9,26.5 20.486,27.086 C42.2
  Top Layer w0.5: v1(12.8,21.5) v1(12.8,27.1) ; C42.2 21.364,27.1 v1(22.35,27.1)
  Bottom Layer w0.5: v1(12.8,21.5) v1(15.35,21.5) ; v1(12.8,27.1) v1(22.35,27.1)
NetD1_1: D1.1 J1.1 | length 7.3
  Top Layer w1.5: J1.1 32.4,13.7 34.82,16.12 D1.1
NetD1_2: D1.2 J1.2 J1.3 | length 11.3
  Top Layer w1.5: J1.2 34,7.5 35.35,8.85 J1.3 35.35,13.1 35.83,13.58 D1.2
NetIC2_1: IC2.1 R31.2 R32.1 | length 8.4
  Top Layer w0.2: R32.1 80.867,10.617 82.05,11.8 82.05,12.759 84.341,15.05 IC2.1
NetIC2_7: IC2.7 K6.1 | length 1.8
  Top Layer w0.2: IC2.7 88.65,14.45 89.05,14.05 K6.1
NetIC2_8: IC2.8 K7.1 | length 2.1
  Top Layer w0.2: IC2.8 89.15,14.6 K7.1
NetIC2_9: IC2.9 R37.2 | length 3.3
  Top Layer w0.3: IC2.9 89.9,15.3 R37.2@91.892,13.308
NetIC2_11: IC2.11 L3.1 | length 10.8
  Top Layer w0.3: IC2.11 91.05,16.8 v1(91.4,16.45) ; v1(91.4,19) L3.1@98.05,19
  Bottom Layer w0.3: v1(91.4,16.45) v1(91.4,19)
NetIC2_13: IC2.13 L4.1 | length 9.4
  Top Layer w0.3: IC2.13 90.55,17.8 90.85,18.1 91.8,18.1 92.1,18.4 95.7,18.4 L4.1@98.067,16.033
NetIC2_19: IC2.19 K4.1 R25.2 | length 10.2
  Top Layer w0.2: IC2.19 88.15,21.384 88.45,21.684 88.45,23.9 89.2,24.65 K4.1 94.333,24.65 R25.2
NetIC2_20: IC2.20 K3.1 R26.2 | length 12.4
  Top Layer w0.2: IC2.20 87.65,21.45 88.05,21.85 88.05,25.6 88.95,26.5 K3.1 R26.2
NetIC2_32: IC2.32 R28.2 R29.1 | length 9.8
  Top Layer w0.2: R28.2 78.817,11.65 81.1,11.65 81.526,12.076 81.526,12.997 84.329,15.8 IC2.32
NetIC3_2: IC3.2 R39.2 | length 4.1
  Top Layer w0.2: IC3.2 16.35,18.517 R39.2
NetIC3_30: IC3.30 R38.2 | length 6.3
  Top Layer w0.2: R38.2 14.55,18.517 14.55,23.8 14.75,24 IC3.30
NetIC4_7: IC4.7 J4.9 | length 23.9
  Top Layer w0.2: v1(19.65,18.7) 19.65,9.8 19.925,9.525 IC4.7
  Bottom Layer w0.2: J4.9@8.128,21.45 J4.9 9.5,20.033 9.5,19.35 10.15,18.7 17.15,18.7 17.65,19.2 19.15,19.2 v1(19.65,18.7)
NetIC4_8: IC4.8 J4.4 | length 19.2
  Top Layer w0.2: v1(20.35,19.35) 20.35,11.25 20.975,10.625 IC4.8
  Bottom Layer w0.2: J4.4@10.994,20.1 J4.4 12.294,20.056 12.75,19.6 20.1,19.6 v1(20.35,19.35)
NetIC4_10: IC4.10 R42.2 | length 6.7
  Top Layer w0.2: IC4.10 16.925,9.525 18.3,10.9 R42.2
NetIC4_11: IC4.11 R41.1 | length 7.4
  Top Layer w0.2: IC4.11 14.375,8.875 14.15,9.1 14.15,10.883 16.5,13.233 R41.1
NetIC4_12: IC4.12 R40.1 | length 7.6
  Top Layer w0.2: R40.1 14.7,12.15 13.75,11.2 13.75,8.8 14.325,8.225 IC4.12
NetIC4_13: IC4.13 J4.3 | length 12.4
  Top Layer w0.2: J4.3 12.8,15.437 12.8,8.8 14.025,7.575 IC4.13
NetIC4_14: IC4.14 J4.2 | length 10.4
  Top Layer w0.2: J4.2 12.4,13.069 12.4,8.25 13.725,6.925 IC4.14
NetJ2_2: J2.2 R5.1 R13.2 | length 7.3
  Top Layer w0.5: R13.2 26.367,25.077 26.79,25.5 28.94,25.5 30,26.56 J2.2
NetJ2_3: J2.3 R4.1 R12.2 | length 9.5
  Top Layer w0.5: R12.2 25.45,22.967 25.45,25.15 26.5,26.2 28.65,26.2 29.2,26.75 J2.3
NetR33_1: R33.1 R34.1 R35.1 R36.1 | length 599.9
  Top Layer w0.4: R36.1 R35.1 129.617,11.767 130.05,12.2 v1(131.15,12.2) ; R34.1 R33.1 129.617,22.933 130.15,22.4 130.8,22.4 131.15,22.75 131.15,32.4 181.3,32.4 181.3,1.9 132.1,1.9 132.1,31.45 180.4,31.45 180.4,2.85 133.05,2.85 133.05,30.5 179.45,30.5 179.45,3.8 134,3.8 134,29.55 178.5,29.55 178.5,4.75 134.95,4.75 v1(134.95,12.2)
  Bottom Layer w0.4: v1(131.15,12.2) v1(134.95,12.2)
NRSTPD: IC2.6 J3.25 R45.2 | length 26
  Top Layer w0.2: R45.2 84.049,9.301 v1(84.75,8.6) ; IC2.6 88.15,12.9 88.95,12.1 v1(88.95,7.65)
  Bottom Layer w0.2: v1(84.75,8.6) 86.4,8.6 87.35,7.65 v1(88.95,7.65) 97.86,7.65 J3.25
USB_N: IC3.15 R13.1 | length 6.8
  Top Layer w0.3: IC3.15 20.6,26 20.7,26.1
  Top Layer w0.5: 20.7,26.1 21.39,26.1 22.05,25.44 22.05,23.6 22.35,23.3 22.97,23.3 23.52,23.85 R13.1
USB_P: IC3.14 R12.1 | length 6.8
  Top Layer w0.3: IC3.14 20.6,25.5 20.7,25.4
  Top Layer w0.5: 20.7,25.4 21.1,25.4 21.35,25.15 21.35,23.31 22.06,22.6 22.97,22.6 23.52,22.05 R12.1
VCC: C26.2 C27.2 C28.2 C35.1 C38.1 IC2.2 IC2.3 IC2.15 IC4.16 K1.1 R3.1 R8.2 R11.2 R16.2 R22.2 R23.2 R28.1 R31.1 R37.1 R43.1 R44.1 R45.1 | length 172.1
  Top Layer w0.2: R45.1 85.536,12.7 C28.2
  Top Layer w0.3: R28.1 R31.1 80.817,12.767 v1(80.85,12.8) ; v1(85.6,13.75) 86.15,14.3 IC2.2 ; IC2.3 86.65,14 v1(86.9,13.75) ; IC2.15 90.45,18.8 90.7,19.05 90.7,19.8
  Top Layer w0.5: IC4.16 15.425,5.075 16.064,4.436 C35.1 ; v1(16.05,2.35) 16.064,2.364 C35.1 ; v1(17.45,2.35) 17.483,2.383 C38.1 C35.1 ; 68.15,19.5 68.183,19.467 R8.2 R16.2 R22.2 ; C28.2 v1(85.6,13.75) ; C27.2 v1(86.9,13.75) ; 90.7,19.8 91.2,20.3 v1(91.7,20.3) C26.2
  Top Layer w0.75: v1(89.75,11.3) v1(90.75,11.3) 91.983,11.3 R37.1 92.3,11.283 93.684,12.667 R23.2
  Top Layer w1: v1(49.15,8.6) v1(50.05,8.6) 53.8,8.6 56.15,10.95 K1.1 ; R43.1 R44.1 56.283,23.017 v1(57,22.3) ; v1(68.15,12.8) v1(69.05,12.8) ; v1(68.15,22.3) v1(69.05,22.3)
  Top Layer w1.5: R11.2 56.133,18.667 K1.1 56.15,21.45 v1(57,22.3) v1(58,22.3) v1(58.95,22.3) ; v1(68.15,12.8) 68.15,19.5 v1(68.15,22.3)
  Bottom Layer w1: v1(16.05,2.35) v1(17.45,2.35) 31.95,2.35 38.2,8.6 v1(49.15,8.6) v1(50.05,8.6) ; v1(69.05,22.3) 73.9,27.15 87.65,27.15 89.25,25.55 89.25,21.35 90.3,20.3 v1(91.7,20.3)
  Bottom Layer w1.5: v1(57,22.3) v1(58,22.3) v1(58.95,22.3) v1(68.15,22.3) v1(69.05,22.3) ; v1(68.15,12.8) v1(69.05,12.8) v1(80.85,12.8) 83.7,12.8 84.65,13.75 v1(85.6,13.75) v1(86.9,13.75) 86.9,13.3 88.9,11.3 v1(89.75,11.3) v1(90.75,11.3)
VMID: C11.1 IC2.16 K5.1 R24.2 | length 11.4
  Top Layer w0.3: IC2.16 89.9,20.4 K5.1 C11.1 93.636,22.65 96.2,22.65 96.6,22.25 R24.2@99.083,22.25
VUSB: C36.1 C37.2 IC3.19 R14.1 | length 28.2
  Top Layer w0.3: C37.2 18.35,28.436 IC3.19
  Top Layer w0.5: v1(13.65,20.25) 13.65,29.65 14.6,30.6 C36.1 16.75,29.15 17.1,28.8 C37.2 ; v1(22.6,20.25) R14.1
  Bottom Layer w0.5: v1(13.65,20.25) v1(22.6,20.25)
pads on no net: FID1.1 FID2.1 FID3.1 IC3.3 IC3.5 IC3.6 IC3.7 IC3.8 IC3.9 IC3.10 IC3.11 IC3.12 IC3.13 IC3.18 IC3.21 IC3.22 IC3.23 IC3.25 IC3.26 IC3.27 IC3.28 IC3.29 IC3.31 IC3.32 IC4.9 J2.10 J2.11 J3.3 J3.4 J3.9 J3.10 J3.11 J3.12 J3.13 J3.14 J3.21 J3.22 J3.23 J3.24 J3.27 J3.29 J3.30 J3.31 J3.32 J3.33 J3.34 J3.35 J3.38 J3.39 J3.42 J3.43 J3.44 J3.45 J3.46 J3.47 J3.48 J3.49 J3.50 J3.51 J3.52 J3.53 J4.1 J4.6 J4.7 J4.8 XT1.2 XT1.4

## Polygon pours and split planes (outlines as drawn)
GND on Bottom Layer "Bot_GND" (solid, remove dead copper, pour order 4): 123.9,34.1 0.5,34.1 0.5,0.5 123.9,0.5
GND on Top Layer "Top_GND" (solid, remove dead copper, pour order 3): 87.75,34.1 0.5,34.1 0.5,0.5 87.448,0.5 87.448,11.519 82.019,11.519 82.019,20.067 87.75,20.067

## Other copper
Top Layer:
  rectangle net GND: 46.2,20.25 52.55,26.15

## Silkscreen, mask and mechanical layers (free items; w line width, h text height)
Top Overlay:
  drawing of 2141 lines, arcs and shapes, not listed
  text "USB" at 54.65,31.45 h1
  text "I2C" at 64.95,31.45 h1
  text "DM" at 59.461,30.81 h1 r90
  text "DP" at 61.976,30.81 h1 r90
  text "SDA" at 69.596,30.81 h1 r90
  text "SCL" at 72.136,30.81 h1 r90
  text "Blueboard PNEV512B Antenna" at 136.75,26.75 h1
  text "AUX2" at 88.8,26.15 h0.9
  text "INTERFACE" at 59.95,24.45 h0.9
  text "I2C" at 69.5,24.45 h0.9
  text "AUX1" at 88.8,24.25 h0.9
  text "CONFIG" at 59.95,23.1 h0.9
  text "CONFIG" at 69.5,23.1 h0.9
  text "VMID" at 89.8,22.65 h0.9
  text "ALE" at 79.45,19.65 h0.9
  text "IRQ" at 18.8,19.4 h0.9 r90
  text "1" at 76,18.75 h0.8 r90
  text "VCC" at 57.95,17.45 h0.9 r90
  text "USB" at 19.66,17.12 h0.8
  text "D5" at 82.35,16.6 h0.9
  text "0" at 76.05,15.7 h0.8 r90
  text "D6" at 82.35,15.2 h0.9
  text "SPI I2C" at 59.7,14.85 h0.8 r90
  text "RS232" at 19.66,14.605 h0.8
  text "A0" at 78.85,13.95 h0.9 r90
  text "A1" at 80.3,13.95 h0.9 r90
  text "D7" at 82.35,13.8 h0.9
  text "1" at 81.55,11.4 h0.8 r90
  text "0" at 81.55,9.6 h0.8 r90
  text "GND" at 46.3,7.9 h0.9
  text "SIGIN" at 89.55,7.7 h0.9 r90
  text "SIGOUT" at 90.85,7.7 h0.9 r90
  text "SPI" at 44.9,2.05 h1
  text "IRQ" at 102.718,1.6 h1 r90
  text "Blueboard PNEV512B" at 59.969,1.499 h1.5
  text "SCK" at 54.508,1.431 h1 r90
  text "v1.5" at 87.274,1.448 h1
  text "MOSI" at 49.327,0.765 h1 r90
  text "MISO" at 51.892,0.598 h1 r90
  text "max. 7.5V" at 25.65,0.55 h0.9 r90
  text "SSEL" at 56.896,0.432 h1 r90
  text "NRST" at 100.228,0.432 h1 r90
Mechanical 1:
  the board outline again, w0.15
Mechanical 3:
  lines w0.15: 0,17.3 183.2,17.3
Mechanical 4:
  text "Master Drawings:" at -48.75,99.25 h2
  text "- material: FR4, Tg: 150" at -48.75,94.85 h2
  text "- thickness: 1.55mm" at -48.75,92.65 h2
  text "- layer stackup: - Top Cu: 35um" at -48.75,90.45 h2
  text "- Bottom Cu: 35um" at -48.65,88.3 h2
  text "- min. hole metalization: 20um" at -48.773,85.798 h2
  text "- surface finishing: ENIG" at -48.773,83.598 h2
  text "- solder mask: - in accordance with IPC-SM-840" at -48.773,79.198 h2
  text "- Liquid Photo Imageable (LPI)" at -48.523,76.998 h2
  text "- color: BLUE" at -48.523,74.798 h2
  text "- unless otherwise defined (in gerber)," at -48.523,72.598 h2
  text "solder mask overlap on SMT pads is not allowed" at -48.423,70.448 h2
  text "- bow and twist: - max. 0.75% SMT boards" at -48.773,61.648 h2
  text "- max. 1.5%  THT boards" at -48.773,59.448 h2
  text "- point of origin (0,0): bottom left corner" at -48.773,57.248 h2
  text "- board is designed on 0.050 mm grid" at -48.773,55.048 h2
  text "- primary side: Top layer" at -48.723,52.848 h2
Mechanical 16:
  drawing of 1453 lines, arcs and shapes, not listed
  text "1" at -30.004,118.661 h1.78
  text "2" at 42.64,118.661 h1.78
  text "3" at 115.792,118.661 h1.78
  text "4" at 188.69,118.661 h1.78
  text "A" at -64.345,95.649 h1.78
  text "A" at 222.675,95.649 h1.78
  text "B" at -64.345,47.592 h1.78
  text "B" at 222.675,47.592 h1.78
  text "C" at -64.345,-0.922 h1.78
  text "C" at 222.675,-0.922 h1.78
  text "D" at -64.345,-48.928 h1.78
  text "D" at 222.675,-48.928 h1.78
  text "Title:" at 133.35,-50.85 h2
  text "Blueboard PNEV512B" at 137.85,-50.85 h5.64
  text "Date:" at 133.35,-54.35 h2
  text "05.04.2013" at 137.85,-54.35 h2
  text "Revision:" at 183.35,-54.35 h2
  text "v1.5" at 190.85,-54.35 h2
  text "File:" at 133.35,-56.85 h2
  text "Blueboard_PNEV512B_v1.5.PcbDoc" at 137.85,-56.85 h2
  text "Designed by:" at 183.35,-56.85 h2
  text "Bostjan Stumpfel/HalC" at 193.85,-56.85 h2
  text "1" at -30.004,-69.299 h1.78
  text "2" at 42.64,-69.299 h1.78
  text "3" at 115.792,-69.299 h1.78
  text "4" at 188.69,-69.299 h1.78
Drill Drawing:
  text ".Legend" at -49,-34.25 h1

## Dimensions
0,0 to 183.2,0 on Mechanical 2
183.2,0 to 183.2,34.6 on Mechanical 2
